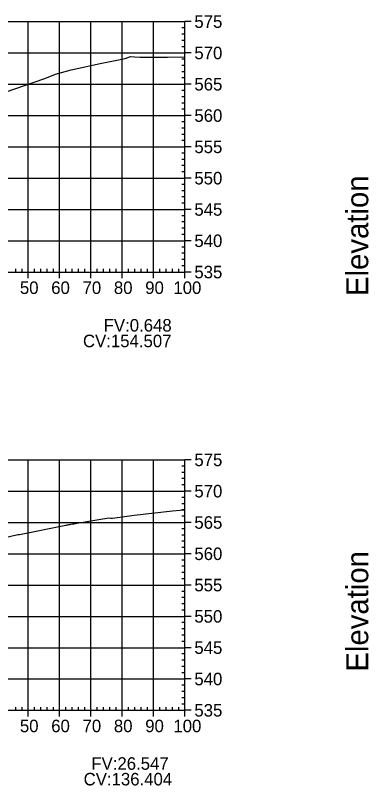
# Model space of a CAD drawing. Extents: x 704834 to 709892, y 372981 to 377533.
# Drawn here: x 706732.8 to 706845.5, y 372988.8 to 373234.8 of the extents above; entities that cross this region are included whole.
import ezdxf

# ---------------------------------------------------------------- set-up
doc = ezdxf.new("R2010")
doc.units = 0
for name, color, linetype in [('57', 7, 'Continuous'), ('59', 7, 'Continuous'), ('60', 7, 'Continuous'), ('Existing', 7, 'Continuous')]:
    doc.layers.add(name, color=color, linetype=linetype)

msp = doc.modelspace()

# ---------------------------------------------------------------- linework, layer by layer
at = {"layer": '57'}
for p, q in [((706586.87, 373232.82), (706786.87, 373232.82)), ((706736.87, 373152.82), (706736.87, 373232.82)), ((706746.87, 373152.82), (706746.87, 373232.82)), ((706756.87, 373152.82), (706756.87, 373232.82)), ((706766.87, 373152.82), (706766.87, 373232.82)), ((706776.87, 373152.82), (706776.87, 373232.82)), ((706786.87, 373152.82), (706786.87, 373232.82)), ((706786.87, 373152.82), (706786.87, 373232.82)), ((706788.87, 373232.82), (706786.87, 373232.82)), ((706786.87, 373230.82), (706785.87, 373230.82)), ((706786.87, 373228.82), (706785.87, 373228.82)), ((706786.87, 373226.82), (706785.87, 373226.82)), ((706786.87, 373224.82), (706785.87, 373224.82)), ((706586.87, 373222.82), (706786.87, 373222.82)), ((706788.87, 373222.82), (706786.87, 373222.82)), ((706786.87, 373220.82), (706785.87, 373220.82)), ((706786.87, 373218.82), (706785.87, 373218.82)), ((706786.87, 373216.82), (706785.87, 373216.82)), ((706786.87, 373214.82), (706785.87, 373214.82)), ((706586.87, 373212.82), (706786.87, 373212.82)), ((706788.87, 373212.82), (706786.87, 373212.82)), ((706786.87, 373210.82), (706785.87, 373210.82)), ((706786.87, 373208.82), (706785.87, 373208.82)), ((706786.87, 373206.82), (706785.87, 373206.82)), ((706786.87, 373204.82), (706785.87, 373204.82)), ((706586.87, 373202.82), (706786.87, 373202.82)), ((706788.87, 373202.82), (706786.87, 373202.82)), ((706786.87, 373200.82), (706785.87, 373200.82)), ((706786.87, 373198.82), (706785.87, 373198.82)), ((706786.87, 373196.82), (706785.87, 373196.82)), ((706786.87, 373194.82), (706785.87, 373194.82)), ((706586.87, 373192.82), (706786.87, 373192.82)), ((706788.87, 373192.82), (706786.87, 373192.82)), ((706786.87, 373190.82), (706785.87, 373190.82)), ((706786.87, 373188.82), (706785.87, 373188.82)), ((706786.87, 373186.82), (706785.87, 373186.82)), ((706786.87, 373184.82), (706785.87, 373184.82)), ((706586.87, 373182.82), (706786.87, 373182.82)), ((706788.87, 373182.82), (706786.87, 373182.82)), ((706786.87, 373180.82), (706785.87, 373180.82)), ((706786.87, 373178.82), (706785.87, 373178.82)), ((706786.87, 373176.82), (706785.87, 373176.82)), ((706786.87, 373174.82), (706785.87, 373174.82)), ((706586.87, 373172.82), (706786.87, 373172.82)), ((706788.87, 373172.82), (706786.87, 373172.82)), ((706786.87, 373170.82), (706785.87, 373170.82)), ((706786.87, 373168.82), (706785.87, 373168.82)), ((706786.87, 373166.82), (706785.87, 373166.82)), ((706786.87, 373164.82), (706785.87, 373164.82)), ((706586.87, 373162.82), (706786.87, 373162.82)), ((706788.87, 373162.82), (706786.87, 373162.82)), ((706786.87, 373160.82), (706785.87, 373160.82)), ((706786.87, 373158.82), (706785.87, 373158.82)), ((706786.87, 373156.82), (706785.87, 373156.82)), ((706586.87, 373152.82), (706786.87, 373152.82)), ((706586.87, 373152.82), (706786.87, 373152.82)), ((706732.87, 373152.82), (706732.87, 373153.82)), ((706734.87, 373152.82), (706734.87, 373153.82)), ((706736.87, 373150.82), (706736.87, 373152.82)), ((706738.87, 373152.82), (706738.87, 373153.82)), ((706740.87, 373152.82), (706740.87, 373153.82)), ((706742.87, 373152.82), (706742.87, 373153.82)), ((706744.87, 373152.82), (706744.87, 373153.82)), ((706746.87, 373150.82), (706746.87, 373152.82)), ((706748.87, 373152.82), (706748.87, 373153.82)), ((706750.87, 373152.82), (706750.87, 373153.82)), ((706752.87, 373152.82), (706752.87, 373153.82)), ((706754.87, 373152.82), (706754.87, 373153.82)), ((706756.87, 373150.82), (706756.87, 373152.82)), ((706758.87, 373152.82), (706758.87, 373153.82)), ((706760.87, 373152.82), (706760.87, 373153.82)), ((706762.87, 373152.82), (706762.87, 373153.82)), ((706764.87, 373152.82), (706764.87, 373153.82)), ((706766.87, 373150.82), (706766.87, 373152.82)), ((706768.87, 373152.82), (706768.87, 373153.82)), ((706770.87, 373152.82), (706770.87, 373153.82)), ((706772.87, 373152.82), (706772.87, 373153.82)), ((706774.87, 373152.82), (706774.87, 373153.82)), ((706776.87, 373150.82), (706776.87, 373152.82)), ((706778.87, 373152.82), (706778.87, 373153.82)), ((706780.87, 373152.82), (706780.87, 373153.82)), ((706782.87, 373152.82), (706782.87, 373153.82)), ((706784.87, 373152.82), (706784.87, 373153.82)), ((706786.87, 373154.82), (706785.87, 373154.82)), ((706786.87, 373150.82), (706786.87, 373152.82)), ((706788.87, 373152.82), (706786.87, 373152.82)), ((706586.87, 373092.82), (706786.87, 373092.82)), ((706736.87, 373012.82), (706736.87, 373092.82)), ((706746.87, 373012.82), (706746.87, 373092.82)), ((706756.87, 373012.82), (706756.87, 373092.82)), ((706766.87, 373012.82), (706766.87, 373092.82)), ((706776.87, 373012.82), (706776.87, 373092.82)), ((706786.87, 373012.82), (706786.87, 373092.82)), ((706786.87, 373012.82), (706786.87, 373092.82)), ((706788.87, 373092.82), (706786.87, 373092.82)), ((706786.87, 373090.82), (706785.87, 373090.82)), ((706786.87, 373088.82), (706785.87, 373088.82)), ((706786.87, 373086.82), (706785.87, 373086.82)), ((706786.87, 373084.82), (706785.87, 373084.82)), ((706586.87, 373082.82), (706786.87, 373082.82)), ((706788.87, 373082.82), (706786.87, 373082.82)), ((706786.87, 373080.82), (706785.87, 373080.82)), ((706786.87, 373078.82), (706785.87, 373078.82)), ((706786.87, 373076.82), (706785.87, 373076.82)), ((706786.87, 373074.82), (706785.87, 373074.82)), ((706586.87, 373072.82), (706786.87, 373072.82)), ((706788.87, 373072.82), (706786.87, 373072.82)), ((706786.87, 373070.82), (706785.87, 373070.82)), ((706786.87, 373068.82), (706785.87, 373068.82)), ((706786.87, 373066.82), (706785.87, 373066.82)), ((706786.87, 373064.82), (706785.87, 373064.82)), ((706586.87, 373062.82), (706786.87, 373062.82)), ((706788.87, 373062.82), (706786.87, 373062.82)), ((706786.87, 373060.82), (706785.87, 373060.82)), ((706786.87, 373058.82), (706785.87, 373058.82)), ((706786.87, 373056.82), (706785.87, 373056.82)), ((706786.87, 373054.82), (706785.87, 373054.82)), ((706586.87, 373052.82), (706786.87, 373052.82)), ((706788.87, 373052.82), (706786.87, 373052.82)), ((706786.87, 373050.82), (706785.87, 373050.82)), ((706786.87, 373048.82), (706785.87, 373048.82)), ((706786.87, 373046.82), (706785.87, 373046.82)), ((706786.87, 373044.82), (706785.87, 373044.82)), ((706586.87, 373042.82), (706786.87, 373042.82)), ((706788.87, 373042.82), (706786.87, 373042.82)), ((706786.87, 373040.82), (706785.87, 373040.82)), ((706786.87, 373038.82), (706785.87, 373038.82)), ((706786.87, 373036.82), (706785.87, 373036.82)), ((706786.87, 373034.82), (706785.87, 373034.82)), ((706586.87, 373032.82), (706786.87, 373032.82)), ((706788.87, 373032.82), (706786.87, 373032.82)), ((706786.87, 373030.82), (706785.87, 373030.82)), ((706786.87, 373028.82), (706785.87, 373028.82)), ((706786.87, 373026.82), (706785.87, 373026.82)), ((706786.87, 373024.82), (706785.87, 373024.82)), ((706586.87, 373022.82), (706786.87, 373022.82)), ((706788.87, 373022.82), (706786.87, 373022.82)), ((706786.87, 373020.82), (706785.87, 373020.82)), ((706786.87, 373018.82), (706785.87, 373018.82)), ((706786.87, 373016.82), (706785.87, 373016.82)), ((706786.87, 373014.82), (706785.87, 373014.82)), ((706586.87, 373012.82), (706786.87, 373012.82)), ((706586.87, 373012.82), (706786.87, 373012.82)), ((706732.87, 373012.82), (706732.87, 373013.82)), ((706734.87, 373012.82), (706734.87, 373013.82)), ((706736.87, 373010.82), (706736.87, 373012.82)), ((706738.87, 373012.82), (706738.87, 373013.82)), ((706740.87, 373012.82), (706740.87, 373013.82)), ((706742.87, 373012.82), (706742.87, 373013.82)), ((706744.87, 373012.82), (706744.87, 373013.82)), ((706746.87, 373010.82), (706746.87, 373012.82)), ((706748.87, 373012.82), (706748.87, 373013.82)), ((706750.87, 373012.82), (706750.87, 373013.82)), ((706752.87, 373012.82), (706752.87, 373013.82)), ((706754.87, 373012.82), (706754.87, 373013.82)), ((706756.87, 373010.82), (706756.87, 373012.82)), ((706758.87, 373012.82), (706758.87, 373013.82)), ((706760.87, 373012.82), (706760.87, 373013.82)), ((706762.87, 373012.82), (706762.87, 373013.82)), ((706764.87, 373012.82), (706764.87, 373013.82)), ((706766.87, 373010.82), (706766.87, 373012.82)), ((706768.87, 373012.82), (706768.87, 373013.82)), ((706770.87, 373012.82), (706770.87, 373013.82)), ((706772.87, 373012.82), (706772.87, 373013.82)), ((706774.87, 373012.82), (706774.87, 373013.82)), ((706776.87, 373010.82), (706776.87, 373012.82)), ((706778.87, 373012.82), (706778.87, 373013.82)), ((706780.87, 373012.82), (706780.87, 373013.82)), ((706782.87, 373012.82), (706782.87, 373013.82)), ((706784.87, 373012.82), (706784.87, 373013.82)), ((706786.87, 373010.82), (706786.87, 373012.82)), ((706788.87, 373012.82), (706786.87, 373012.82))]:
    msp.add_line(p, q, dxfattribs=at)
at = {"layer": 'Existing'}
for points in [[(706729.52, 373210.26), (706742.13, 373214.63), (706745.53, 373216.04), (706750.53, 373217.47), (706759.83, 373219.41), (706767.79, 373221.08), (706768.61, 373221.36), (706769.45, 373221.64), (706770.79, 373221.59), (706772.49, 373221.49), (706781.25, 373221.52), (706786.87, 373221.6)], [(706722.65, 373066.43), (706733.57, 373068.93), (706733.88, 373068.98), (706733.91, 373068.99), (706733.95, 373069), (706734.06, 373069.02), (706748.8, 373071.96), (706749.03, 373072.01), (706749.27, 373072.05), (706749.53, 373072.1), (706749.81, 373072.15), (706750.12, 373072.2), (706750.48, 373072.26), (706750.92, 373072.34), (706751.51, 373072.44), (706752.34, 373072.58), (706753.74, 373072.82), (706756.86, 373073.35), (706762.58, 373074.31), (706763.21, 373074.19), (706763.31, 373074.18), (706763.43, 373074.2), (706763.6, 373074.22), (706763.74, 373074.23), (706770.61, 373075.17), (706782.88, 373076.57), (706785.36, 373076.74), (706786.87, 373076.84)]]:
    msp.add_lwpolyline(points, dxfattribs=at)

# ---------------------------------------------------------------- texts
for s, p in [('CV:154.507', (706754.31, 373128.82)), ('CV:136.404', (706754.53, 372988.82))]:
    msp.add_text(s, height=4).set_placement(p)
at = {"layer": '57'}
for s, p in [('575', (706789.87, 373230.82)), ('570', (706789.87, 373220.82)), ('565', (706789.87, 373210.82)), ('560', (706789.87, 373200.82)), ('555', (706789.87, 373190.82)), ('550', (706789.87, 373180.82)), ('545', (706789.87, 373170.82)), ('540', (706789.87, 373160.82)), ('535', (706789.87, 373150.82)), ('50', (706734.18, 373145.82)), ('60', (706744.18, 373145.82)), ('70', (706754.18, 373145.82)), ('80', (706764.18, 373145.82)), ('90', (706774.18, 373145.82)), ('100', (706783.17, 373145.82)), ('575', (706789.87, 373090.82)), ('570', (706789.87, 373080.82)), ('565', (706789.87, 373070.82)), ('560', (706789.87, 373060.82)), ('555', (706789.87, 373050.82)), ('550', (706789.87, 373040.82)), ('545', (706789.87, 373030.82)), ('540', (706789.87, 373020.82)), ('535', (706789.87, 373010.82)), ('50', (706734.18, 373005.82)), ('60', (706744.18, 373005.82)), ('70', (706754.18, 373005.82)), ('80', (706764.18, 373005.82)), ('90', (706774.18, 373005.82)), ('100', (706783.17, 373005.82))]:
    msp.add_text(s, height=4, dxfattribs=at).set_placement(p)
at = {"layer": '59'}
for s, p in [('FV:0.648', (706760.92, 373133.82)), ('FV:26.547', (706756.99, 372993.82))]:
    msp.add_text(s, height=4, dxfattribs=at).set_placement(p)
at = {"layer": '60'}
for p in [(706845.37, 373145.18), (706845.37, 373025.18)]:
    msp.add_text('Elevation', height=7, rotation=90, dxfattribs=at).set_placement(p)

doc.saveas('drawing.dxf')
